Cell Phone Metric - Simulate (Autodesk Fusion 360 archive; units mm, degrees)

design "Cell Phone Metric - Final" references "Cell Phone Stand - Metric Assembly", "Vise"
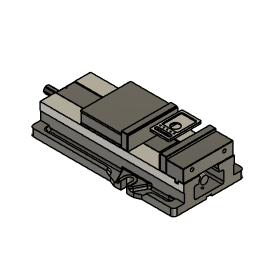
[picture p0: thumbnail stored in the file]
external_derived "ExternalDerived1"
align "Align1"
sketch "Sketch1" plane through (0, 0, 0) normal (0, 0, -1) x axis (1, 0, 0)
  line L1 (30, 46.5) -> (30, -46.5)
  line L2 (-26.5, 50) -> (26.5, 50)
  line L3 (-30, -46.5) -> (-30, 46.5)
  line L4 (26.5, -50) -> (-26.5, -50)
  line L5 (-23.5, 38.5) -> (-23.5, 36)
  line L6 (20, 42) -> (-20, 42)
  line L7 (23.5, 36) -> (23.5, 38.5)
  line L8 (-20, 32.5) -> (20, 32.5)
  line L9 (-50.8, -55) -> (50.8, -55)
  line L10 (-50.8, 55) -> (-50.8, -55)
  line L11 (50.8, 55) -> (-50.8, 55)
  line L12 (50.8, -55) -> (50.8, 55)
  line L13 (-50.8, 55) -> (50.8, -55)
  line L14 (50.8, 55) -> (-50.8, -55)
  arc A1 centre (26.5, -46.5) radius 3.5 clockwise from (30, -46.5) to (26.5, -50)
  arc A2 centre (26.5, 46.5) radius 3.5 clockwise from (26.5, 50) to (30, 46.5)
  arc A3 centre (-26.5, 46.5) radius 3.5 clockwise from (-30, 46.5) to (-26.5, 50)
  arc A4 centre (-26.5, -46.5) radius 3.5 clockwise from (-26.5, -50) to (-30, -46.5)
  circle C1 centre (10.5, 25) radius 2.117
  circle C2 centre (-10.5, 25) radius 2.117
  circle C3 centre (-21, 25) radius 2.117
  circle C4 centre (0, 25) radius 2.117
  circle C5 centre (21, 25) radius 2.117
  arc A5 centre (-20, 38.5) radius 3.5 clockwise from (-23.5, 38.5) to (-20, 42)
  arc A6 centre (20, 38.5) radius 3.5 clockwise from (20, 42) to (23.5, 38.5)
  arc A7 centre (20, 36) radius 3.5 clockwise from (23.5, 36) to (20, 32.5)
  arc A8 centre (-20, 36) radius 3.5 clockwise from (-20, 32.5) to (-23.5, 36)
  circle C6 centre (0, 0) radius 12.5
  point P36 (0, 0)
  point P1 (0, 0)
  point P34 (-50.8, 55)
  point P35 (50.8, 55)
  point P32 (50.8, -55)
  horizontal L9
  perpendicular L9 L10
  parallel L9 L11
  parallel L10 L12
  coincident L13 P36
  coincident L14 P36
  coincident P1 P36
  dimension "d1" distance P34 P35 = 101.6
  dimension "d2" distance P32 P35 = 110
extrude "Extrude1" new body sketch "Sketch1" profile of L9 L10 L11 L12 against normal blind 6 bodies "Stock"
component_insert "Component Insert"
position "Position1"
ground "Pin"
position "Position2"
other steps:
derived_base_feature "Derived Base Feature" bodies "Main Body"
named bodies: "Main Body", "Stock"

design "Cell Phone Stand - Metric Assembly"
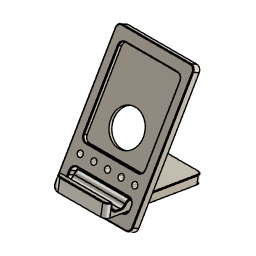
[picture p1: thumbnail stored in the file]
sketch "Main Body Sketch" plane through (0, 0, 0) normal (0, 1, 0) x axis (1, 0, 0)
  line L1 (30, 0) -> (-30, 0)
  line L2 (30, -100) -> (30, 0)
  line L3 (-30, -100) -> (30, -100)
  line L4 (-30, 0) -> (-30, -100)
  line L5 (30, -100) -> (-30, 0)
  line L6 (-30, -100) -> (30, 0)
  line L7 (23.5, -17.5) -> (-23.5, -17.5)
  line L8 (23.5, -8) -> (23.5, -17.5)
  line L9 (-23.5, -8) -> (23.5, -8)
  line L10 (-23.5, -17.5) -> (-23.5, -8)
  line L11 (0, 0) -> (0, -8)
  line L12 (23.5, -92) -> (-23.5, -92)
  line L13 (23.5, -32) -> (23.5, -92)
  line L14 (-23.5, -32) -> (23.5, -32)
  line L15 (-23.5, -92) -> (-23.5, -32)
  line L16 (0, -62.5) -> (0, -50)
  line L17 (17.2022, -62.0451) -> (0, -50)
  line L18 (21, -50) -> (0, -50)
  line L19 (17.2022, -37.9549) -> (0, -50)
  circle C1 centre (0, -50) radius 12.5
  point P6 (0, -50)
  point P1 (0, 0)
  point P11 (0, -8)
  point P12 (0, 0)
  point P17 (0, -50)
  point P21 (0, -50)
  point P22 (0, -62.5)
  point P18 (17.2022, -62.0451)
  point P23 (17.2022, -62.0451)
  point P19 (21, -50)
  point P24 (21, -50)
  point P25 (0, -50)
  point P20 (17.2022, -37.9549)
  point P26 (17.2022, -37.9549)
  point P27 (-17.2022, -62.0451)
  point P28 (-21, -50)
  point P29 (-17.2022, -37.9549)
  point P30 (0, -25)
  point P4 (30, -100)
  point P5 (-30, -100)
  point P3 (30, 0)
  point P8 (23.5, -17.5)
  point P9 (23.5, -8)
  point P7 (-23.5, -17.5)
  point P14 (23.5, -92)
  point P15 (23.5, -32)
  horizontal L1
  perpendicular L1 L2
  parallel L1 L3
  parallel L2 L4
  coincident L5 P6
  coincident L6 P6
  midpoint P1 L1
  horizontal L7
  vertical L8
  horizontal L9
  vertical L10
  midpoint L9 P11
  coincident P1 P12
  vertical L11
  horizontal L12
  vertical L13
  horizontal L14
  vertical L15
  collinear L8 L13
  collinear L10 L15
  coincident P6 P17
  coincident P6 P21
  coincident C1 P22
  vertical L16
  coincident P18 P23
  coincident P19 P24
  perpendicular L16 L18
  coincident P17 P25
  coincident P20 P26
  equal L17 L18
  equal L18 L19
  symmetric P18 L16 P27
  symmetric P19 L16 P28
  symmetric P20 L16 P29
  vertical P6 P30
  dimension "d1" distance P4 P5 = 60
  dimension "d2" distance P3 P4 = 100
  dimension "d3" distance P8 P9 = 9.5
  dimension "d4" distance L1 L9 = 8
  dimension "d5" distance P7 P8 = 47
  dimension "d6" distance L3 L12 = 8 (= "d4")
  dimension "d7" distance P14 P15 = 60
  dimension "d8" diameter C1 = 25
  dimension "d9" distance P21 P24 = 21
  dimension "d10" angle L17 L18 = 35
  dimension "d11" angle L18 L19 = 35 (= "d10")
  dimension "d12" distance P17 P30 = 25
  dimension "d15" R-Pattern1-uDistance = 21
  dimension "d16" R-Pattern1-vDistance = 0
extrude "Extrude1" new body sketch "Main Body Sketch" profile of L1 L2 L3 L4 L7 L8 L9 L10 L12 L13 L14 L15 C1 along normal blind 5.5
extrude "Extrude2" cut sketch "Main Body Sketch" profile of L12 L13 L14 L15 C1 along normal blind 3
hole "Hole2" HoleDiameter 4.234 TipAngle 118
fillet "Fillet1" radius 3.5
chamfer "Chamfer1" distance 0.5
move "Move1"
sketch "Stand Body Sketch" plane through (0, 0, 0) normal (1, 0, 0) x axis (0, 1, 0)
  line L1 (14.7999, 15.9408) -> (10.4698, 18.4408)
  line L2 (5.7198, 10.2135) -> (10.0499, 7.7135)
  line L3 (66.5456, 2.9579) -> (12.5794, 12.0948)
  line L4 (66.0448, 0) -> (66.5456, 2.9579)
  line L5 (-7.9029, 12.52) -> (66.0448, 0)
  line L6 (-6.317, 21.8867) -> (-7.9029, 12.52)
  line L7 (-2.3731, 21.2189) -> (-6.317, 21.8867)
  line L8 (-2.3281, 14.6188) -> (-2.3731, 21.2189)
  line L9 (6.5456, 13.1164) -> (-2.3281, 14.6188)
  line L10 (8.7802, 17.0486) -> (6.5456, 13.1164)
  line L11 (16.0467, 18.1003) -> (19.9906, 17.4326)
  line L12 (24.2831, 10.1133) -> (19.9906, 17.4326)
  line L13 (16.0467, 18.1003) -> (12.5794, 12.0948)
  line L14 (54.2999, 84.3568) -> (7.7999, 3.8164)
  line L15 (13.6992, 16.2157) -> (8.7802, 17.0486)
  line L16 (12.1028, 18.768) -> (11.7272, 16.5496)
  line L17 (16.0467, 18.1003) -> (12.1028, 18.768)
  line L18 (15.6711, 15.8819) -> (16.0467, 18.1003)
  line L19 (67.0881, 6.1623) -> (22.1368, 13.7729)
  line L20 (66.5456, 2.9579) -> (67.0881, 6.1623)
  circle C1 centre (13.6992, 16.2157) radius 2
  point P17 (24.2831, 10.1133)
  point P16 (16.0467, 18.1003)
  point P1 (0, 0)
  point P8 (66.0448, 0)
  point P18 (16.0467, 18.1003)
  point P5 (5.7198, 10.2135)
  point P23 (11.7272, 16.5496)
  point P26 (15.6711, 15.8819)
  point P21 (13.6992, 16.2157)
  point P22 (13.6992, 16.2157)
  point P25 (16.0467, 18.1003)
  point P28 (22.1368, 13.7729)
  point P30 (66.5456, 2.9579)
  point P7 (66.5456, 2.9579)
  point P9 (-7.9029, 12.52)
  point P10 (-6.317, 21.8867)
  point P11 (-2.3731, 21.2189)
  point P12 (-2.3281, 14.6188)
  point P13 (6.5456, 13.1164)
  point P15 (19.9906, 17.4326)
  point P14 (8.7802, 17.0486)
  point P27 (6.0499, 0.7853)
  perpendicular L3 L4
  perpendicular L5 L6
  perpendicular L6 L7
  parallel L3 L9
  coincident L3 P17
  collinear L7 L11
  perpendicular L1 L13
  coincident P16 L13
  parallel L3 L5
  horizontal P1 P8
  collinear L3 L9
  coincident P16 P18
  collinear L13 L14
  coincident P5 L5
  parallel L5 L15
  coincident C1 P23
  perpendicular L16 L17
  coincident C1 P26
  tangent C1 L18
  perpendicular L17 L18
  tangent C1 L16
  parallel L6 L16
  coincident P21 P22
  collinear L11 L17
  coincident P18 P25
  midpoint L12 P28
  perpendicular L4 L19
  coincident L3 P30
  perpendicular L3 L20
  coincident P7 P30
  dimension "d30" distance P8 P9 = 75
  dimension "d31" distance P7 P8 = 3
  dimension "d32" distance P9 P10 = 9.5
  dimension "d33" angle L11 L12 = 50
  dimension "d34" distance P10 P11 = 4
  dimension "d35" distance P12 P13 = 9
  dimension "d36" distance P15 P16 = 4
  dimension "d37" distance L9 P14 = 4.25
  dimension "d38" angle L9 L10 = 70
  dimension "d39" angle L8 L9 = 100
  dimension "d40" diameter C1 = 4
  dimension "d41" distance P8 P27 = 60
extrude "Extrude3" new body sketch "Stand Body Sketch" profile of L3 L4 L5 L6 L7 L8 L9 L10 L11 L12 L13 L14 L15 C1 L18 L19 L20 distance 40
fillet "Fillet2" radius 3.5
chamfer "Chamfer2" distance 0.5
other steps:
thread "Thread1" ThreadOffset 0 ThreadDepth 7.4
named bodies: "Main Body", "Stand Body"

design "Vise"
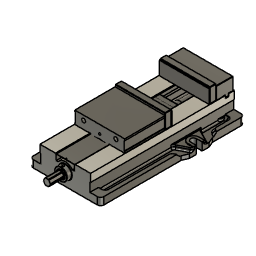
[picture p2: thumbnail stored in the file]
description: HaasClamp
base_feature "Base Feature1"
base_feature "Base Feature1"
base_feature "Base Feature1"
base_feature "Base Feature1"
base_feature "Base Feature1"
base_feature "Base Feature1"
base_feature "Base Feature1"
base_feature "Base Feature1"
base_feature "Base Feature1"
base_feature "Base Feature1"
as_built_joint "As-built1"
as_built_joint "As-built2"
as_built_joint "As-built3"
joint_origin "JointOrigin1" OffsetX 0 OffsetY 0 OffsetZ 0 AngleZ 0
joint "Assemble1" alignAngle 180 alignOffsetX 0 alignOffsetY 0 alignOffsetZ 0 (= "jaw_width_haas_050002") SlideMaximum 22.5 SlideMinimum 0
position "Position1"
sketch "Sketch1" plane through (0, -72.5, 0) normal (0, -1, 0) x axis (1, 0, 0)
  line L1 (75, 73) -> (-75, 73)
  line L2 (76, 74) -> (75, 73)
  line L3 (76, 116.5) -> (76, 74)
  line L4 (75, 117.5) -> (76, 116.5)
  line L5 (-75, 117.5) -> (75, 117.5)
  line L6 (-76, 116.5) -> (-75, 117.5)
  line L7 (-76, 74) -> (-76, 116.5)
  line L8 (-75, 73) -> (-76, 74)
  line L9 (76.4, 114.275) -> (-76, 114.275)
  line L10 (76.4, 73) -> (76.4, 114.275)
  line L11 (-76, 73) -> (76.4, 73)
  line L12 (-76, 114.275) -> (-76, 73)
  circle C1 centre (49.21, 96.8) radius 11
  circle C2 centre (-49.21, 96.8) radius 11
  point P14 (76.4, 73)
  point P12 (-76, 114.275)
  point P13 (76.4, 114.275)
  horizontal L9
  vertical L10
  horizontal L11
  vertical L12
  coincident L1 P14
  coincident L7 P12
  dimension "d16" distance P12 P13 = 152.4
  dimension "d17" distance P13 P14 = 41.275
place_component sketch "Sketch1"
extrude "Extrude1" new body sketch "Sketch1" profile of L1 L2 L3 L7 L8 C1 C2 L9 L11 L12 along normal blind 3.175
place_component sketch "Sketch1"
extrude "Extrude1" sketch "Sketch1" profile of L1 L2 L3 L7 L8 C1 C2 L9 L11 L12 blind -3.175
as_built_joint "As-built5"
as_built_joint "As-built6"
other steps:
create_component "CreateComponent1"
create_component "CreateComponent2"
create_component "CreateComponent3"
create_component "CreateComponent4"
create_component "CreateComponent5"
create_component "CreateComponent6"
create_component "CreateComponent7"
create_component "CreateComponent8"
create_component "CreateComponent9"
create_component "CreateComponent10"
joint_origin "JointOrigin10"
joint_origin "JointOrigin11"
create_component "CreateComponent11" sketch "Sketch1"
create_component "CreateComponent12" sketch "Sketch1"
